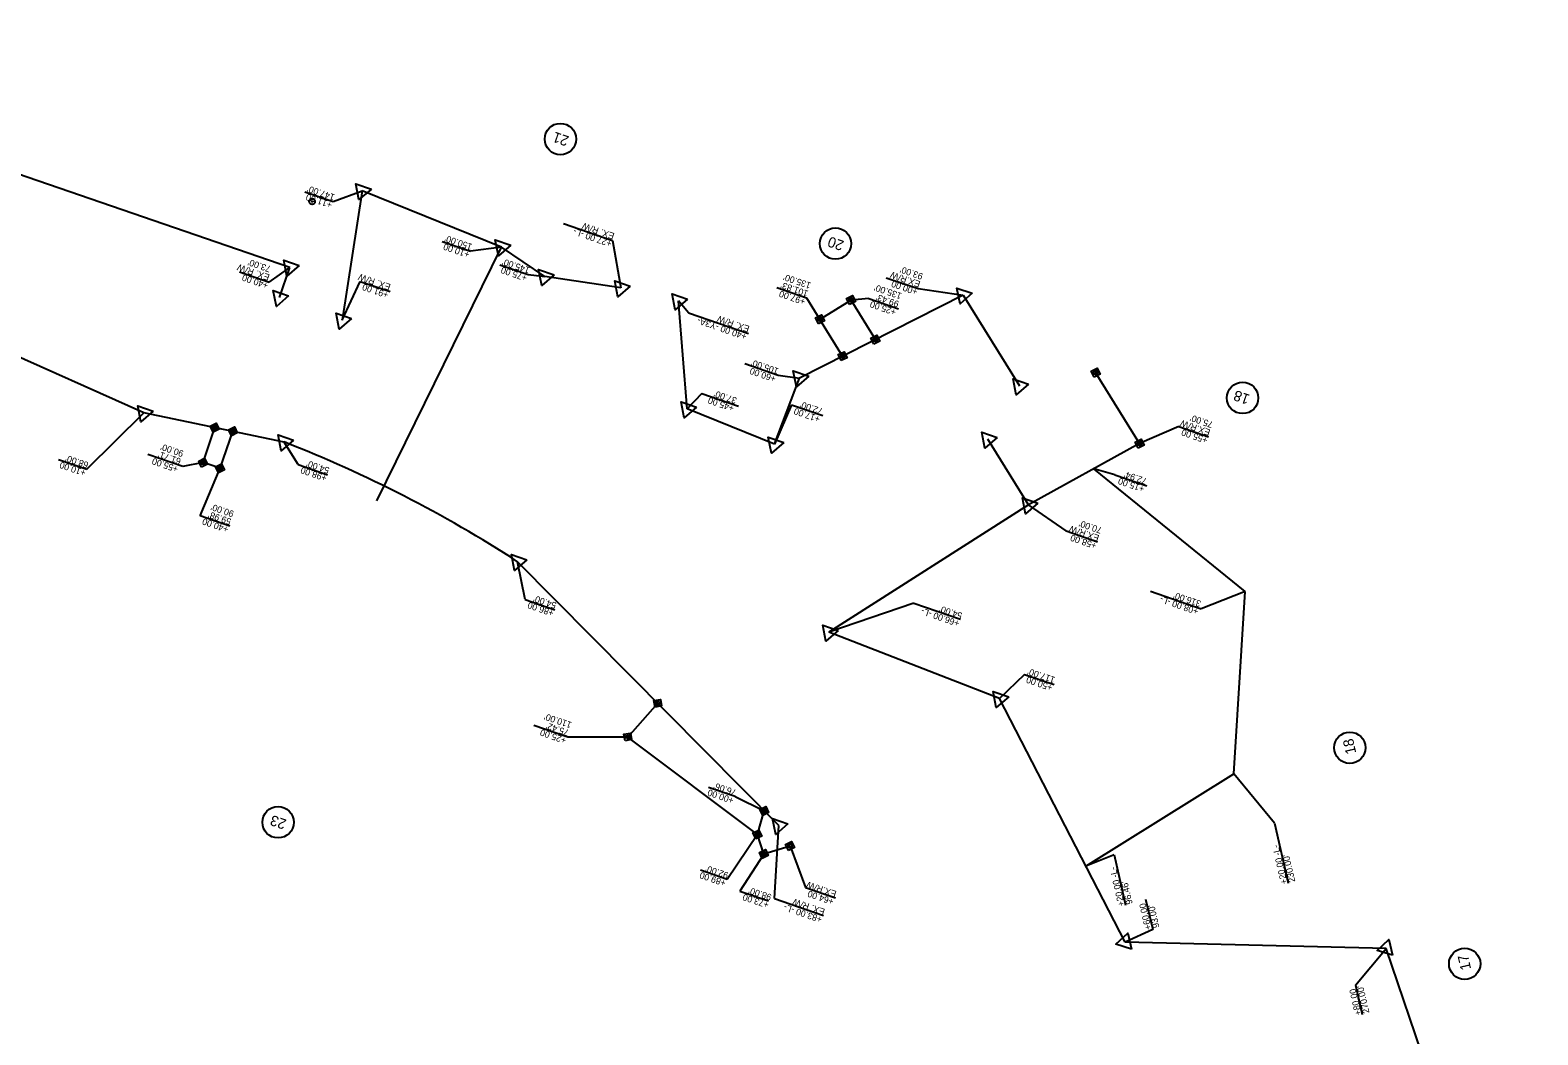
# Model space of a CAD drawing. Extents: x 474184 to 481900, y 489262 to 505659.
# Drawn here: x 480329 to 481484, y 492769 to 493539 of the extents above; entities that cross this region are included whole.
import ezdxf

# ---------------------------------------------------------------- set-up
doc = ezdxf.new("R2010")
doc.units = 0
for name, color, linetype in [('Default', 7, 'Continuous'), ('Prop Drainage Structure Drop Inlet Grate 2 Wide Slots and Sag Grates 840 22 CELL', 7, 'Continuous'), ('Prop Drainage Structure Outlet Berm Ditch 850 10 Label', 7, 'Continuous'), ('Prop Drainage Structure Pipe CSP 15in', 7, 'Continuous'), ('Prop Drainage Structure Pipe RCP 18in Class IV', 7, 'Continuous'), ('Prop Drainage Structure Pipe RCP 18in Class IV Label', 7, 'Continuous'), ('Prop Drainage Structure Pipe Side Drain 15in Label', 7, 'Continuous'), ('Prop Drainage Structure Pipe Stub Out CELL', 7, 'Continuous'), ('Prop Drainage Structure Plot Symbol 50 Scale', 7, 'Continuous'), ('Prop Earthen Structure Base Ditch Lateral Detail Label', 7, 'Continuous'), ('Prop Earthen Structure False Sump CELL', 7, 'Continuous'), ('Prop Earthen Structure False Sump Label', 7, 'Continuous'), ('Sheet Plot Border Outside CELL', 7, 'Continuous')]:
    doc.layers.add(name, color=color, linetype=linetype)

msp = doc.modelspace()

# ---------------------------------------------------------------- linework, layer by layer
at = {"layer": 'Default'}
for radius in [2.18, 0.24]:
    msp.add_circle((480544.7, 493407.3), radius, dxfattribs=at)
at = {"layer": 'Prop Drainage Structure Drop Inlet Grate 2 Wide Slots and Sag Grates 840 22 CELL'}
for p, q in [((480957.5, 493331.9), (480933.7, 493317.1)), ((480976.2, 493301.6), (480957.5, 493331.9)), ((480951.1, 493288.9), (480933.7, 493317.1)), ((481178.6, 493221.9), (481144.9, 493276.3)), ((481178.6, 493221.9), (481093.5, 493175)), ((480786.5, 492997.2), (480809.4, 493023.1)), ((480885.8, 492922.5), (480786.5, 492997.2))]:
    msp.add_line(p, q, dxfattribs=at)
at = {"layer": 'Prop Drainage Structure Outlet Berm Ditch 850 10 Label'}
for p, q in [((480461.2, 493207.4), (480470.1, 493234.2)), ((480474.2, 493203), (480484, 493231.3)), ((480474.2, 493203), (480461.2, 493207.4)), ((480885.8, 492922.5), (480891, 492940.7)), ((480890.7, 492907.6), (480885.8, 492922.5)), ((480910.8, 492913.7), (480890.7, 492907.6))]:
    msp.add_line(p, q, dxfattribs=at)
at = {"layer": 'Prop Drainage Structure Pipe CSP 15in'}
for p, q in [((480734.9, 493455.2), (480734.9, 493455.2)), ((480945.6, 493375.1), (480945.6, 493375.1)), ((481257.5, 493256.9), (481257.5, 493256.9)), ((481339.6, 492989), (481339.6, 492989)), ((480518.6, 492931.9), (480518.6, 492931.9)), ((481427.6, 492823.5), (481427.6, 492823.5))]:
    msp.add_line(p, q, dxfattribs=at)
for centre in [(480734.9, 493455.2), (480945.6, 493375.1), (481257.5, 493256.9), (481339.6, 492989), (480518.6, 492931.9), (481427.6, 492823.5)]:
    msp.add_circle(centre, 12, dxfattribs=at)
at = {"layer": 'Prop Drainage Structure Pipe RCP 18in Class IV'}
for p, q in [((480583, 493415.6), (480583, 493415.6)), ((480689.8, 493372.5), (480689.8, 493372.5)), ((480527.7, 493356.9), (480527.7, 493356.9)), ((480723, 493349.9), (480723, 493349.9)), ((480519.6, 493333.8), (480519.6, 493333.8)), ((480781.2, 493341.2), (480781.2, 493341.2)), ((480825.3, 493331.2), (480825.3, 493331.2)), ((480957.5, 493331.9), (480957.5, 493331.9)), ((481043.3, 493335.7), (481043.3, 493335.7)), ((480567.8, 493316.4), (480567.8, 493316.4)), ((480933.7, 493317.1), (480933.7, 493317.1)), ((480976.2, 493301.6), (480976.2, 493301.6)), ((480951.1, 493288.9), (480951.1, 493288.9)), ((480918, 493272.1), (480918, 493272.1)), ((481144.9, 493276.3), (481144.9, 493276.3)), ((481086.5, 493266.1), (481086.5, 493266.1)), ((480415.9, 493245.5), (480415.9, 493245.5)), ((480832.1, 493248.5), (480832.1, 493248.5)), ((480470.1, 493234.2), (480470.1, 493234.2)), ((480484, 493231.3), (480484, 493231.3)), ((480523.4, 493223.1), (480523.4, 493223.1)), ((480898.9, 493221.4), (480898.9, 493221.4)), ((481062.4, 493225.3), (481062.4, 493225.3)), ((481178.6, 493221.9), (481178.6, 493221.9)), ((480461.2, 493207.4), (480461.2, 493207.4)), ((480474.2, 493203), (480474.2, 493203)), ((481093.5, 493175), (481093.5, 493175)), ((480702.1, 493131.5), (480702.1, 493131.5)), ((480940.5, 493077.5), (480940.5, 493077.5)), ((480809.4, 493023.1), (480809.4, 493023.1)), ((481071.2, 493026.6), (481071.2, 493026.6)), ((480786.5, 492997.2), (480786.5, 492997.2)), ((480891, 492940.7), (480891, 492940.7)), ((480902.2, 492929.4), (480902.2, 492929.4)), ((480885.8, 492922.5), (480885.8, 492922.5)), ((480890.7, 492907.6), (480890.7, 492907.6)), ((480910.8, 492913.7), (480910.8, 492913.7)), ((481167.4, 492840.1), (481167.4, 492840.1)), ((481367.5, 492835.2), (481367.5, 492835.2))]:
    msp.add_line(p, q, dxfattribs=at)
for points in [[(480590.1, 493416.9), (480580.6, 493408.8), (480578.2, 493421)], [(480696.9, 493373.9), (480687.4, 493365.7), (480685, 493378)], [(480534.7, 493358.3), (480525.3, 493350.1), (480522.9, 493362.4)], [(480730.1, 493351.3), (480720.6, 493343.1), (480718.2, 493355.3)], [(480788.3, 493342.5), (480778.9, 493334.4), (480776.5, 493346.6)], [(480526.7, 493335.1), (480517.3, 493327), (480514.9, 493339.2)], [(480832.3, 493332.6), (480822.9, 493324.4), (480820.5, 493336.6)], [(481050.4, 493337.1), (481041, 493328.9), (481038.6, 493341.1)], [(480574.9, 493317.8), (480565.5, 493309.6), (480563.1, 493321.9)], [(480925.1, 493273.5), (480915.7, 493265.3), (480913.3, 493277.6)], [(481093.6, 493267.5), (481084.1, 493259.3), (481081.7, 493271.5)], [(480423, 493246.8), (480413.6, 493238.7), (480411.2, 493250.9)], [(480839.2, 493249.9), (480829.8, 493241.7), (480827.4, 493253.9)], [(480530.5, 493224.5), (480521, 493216.3), (480518.6, 493228.6)], [(480906, 493222.8), (480896.5, 493214.6), (480894.1, 493226.8)], [(481069.5, 493226.6), (481060, 493218.5), (481057.6, 493230.7)], [(481100.6, 493176.4), (481091.2, 493168.2), (481088.8, 493180.5)], [(480709.2, 493132.8), (480699.8, 493124.7), (480697.4, 493136.9)], [(480947.6, 493078.8), (480938.2, 493070.6), (480935.8, 493082.9)], [(481078.3, 493028), (481068.8, 493019.8), (481066.5, 493032.1)], [(480909.2, 492930.8), (480899.8, 492922.6), (480897.4, 492934.9)], [(481172.3, 492834.8), (481160.4, 492838.5), (481169.5, 492847)], [(481372.4, 492830), (481360.5, 492833.6), (481369.6, 492842.1)]]:
    msp.add_lwpolyline(points, close=True, dxfattribs=at)
at = {"layer": 'Prop Drainage Structure Pipe RCP 18in Class IV Label'}
for points in [[(480956.3, 493328.5), (480954.1, 493333), (480958.6, 493335.3), (480960.9, 493330.7)], [(480956.9, 493330.2), (480955.8, 493332.5), (480958, 493333.6), (480959.2, 493331.3)], [(480932.5, 493313.7), (480930.3, 493318.3), (480934.8, 493320.5), (480937.1, 493315.9)], [(480933.1, 493315.4), (480932, 493317.7), (480934.2, 493318.8), (480935.4, 493316.5)], [(480975, 493298.2), (480972.8, 493302.8), (480977.4, 493305), (480979.6, 493300.5)], [(480975.6, 493299.9), (480974.5, 493302.2), (480976.8, 493303.3), (480977.9, 493301)], [(480950, 493285.5), (480947.7, 493290.1), (480952.3, 493292.3), (480954.5, 493287.7)], [(480950.6, 493287.2), (480949.4, 493289.5), (480951.7, 493290.6), (480952.8, 493288.3)], [(481143.7, 493272.9), (481141.5, 493277.4), (481146.1, 493279.7), (481148.3, 493275.1)], [(481144.3, 493274.6), (481143.2, 493276.9), (481145.5, 493278), (481146.6, 493275.7)], [(480468.9, 493230.8), (480466.7, 493235.4), (480471.3, 493237.6), (480473.5, 493233)], [(480469.5, 493232.5), (480468.4, 493234.8), (480470.7, 493235.9), (480471.8, 493233.6)], [(480482.9, 493227.9), (480480.6, 493232.5), (480485.2, 493234.7), (480487.4, 493230.2)], [(480483.4, 493229.6), (480482.3, 493231.9), (480484.6, 493233), (480485.7, 493230.7)], [(481177.4, 493218.5), (481175.2, 493223.1), (481179.8, 493225.3), (481182, 493220.7)], [(481178, 493220.2), (481176.9, 493222.5), (481179.2, 493223.6), (481180.3, 493221.3)], [(480460, 493204), (480457.8, 493208.5), (480462.3, 493210.8), (480464.6, 493206.2)], [(480460.6, 493205.7), (480459.5, 493208), (480461.8, 493209.1), (480462.9, 493206.8)], [(480473, 493199.6), (480470.8, 493204.1), (480475.3, 493206.4), (480477.6, 493201.8)], [(480473.6, 493201.3), (480472.5, 493203.5), (480474.8, 493204.7), (480475.9, 493202.4)], [(480807.4, 493020.1), (480806.5, 493025.1), (480811.5, 493026), (480812.4, 493021)], [(480808.4, 493021.6), (480807.9, 493024.1), (480810.4, 493024.6), (480810.9, 493022.1)], [(480784.4, 492994.3), (480783.5, 492999.3), (480788.5, 493000.2), (480789.4, 492995.2)], [(480785.4, 492995.7), (480785, 492998.2), (480787.5, 492998.7), (480787.9, 492996.2)], [(480889.9, 492937.2), (480887.6, 492941.8), (480892.2, 492944.1), (480894.4, 492939.5)], [(480890.4, 492939), (480889.3, 492941.2), (480891.6, 492942.4), (480892.7, 492940.1)], [(480884.6, 492919.1), (480882.4, 492923.7), (480886.9, 492925.9), (480889.2, 492921.3)], [(480885.2, 492920.8), (480884.1, 492923.1), (480886.3, 492924.2), (480887.5, 492921.9)], [(480909.7, 492910.3), (480907.4, 492914.8), (480912, 492917.1), (480914.2, 492912.5)], [(480910.2, 492912), (480909.1, 492914.2), (480911.4, 492915.4), (480912.5, 492913.1)], [(480889.5, 492904.2), (480887.3, 492908.7), (480891.9, 492911), (480894.1, 492906.4)], [(480890.1, 492905.9), (480889, 492908.1), (480891.3, 492909.3), (480892.4, 492907)]]:
    msp.add_lwpolyline(points, close=True, dxfattribs=at)
at = {"layer": 'Prop Drainage Structure Pipe Side Drain 15in Label'}
for p, q in [((480527.7, 493356.9), (479998.1, 493538.6)), ((480689.8, 493372.5), (480583, 493415.6)), ((480723, 493349.9), (480689.8, 493372.5)), ((480519.6, 493333.8), (480527.7, 493356.9)), ((480781.2, 493341.2), (480723, 493349.9)), ((480832.1, 493248.5), (480825.3, 493331.2)), ((481043.3, 493335.7), (480918, 493272.1)), ((481043.3, 493335.7), (481086.5, 493266.1)), ((480415.9, 493245.5), (480241.2, 493323.4)), ((480898.9, 493221.4), (480918, 493272.1)), ((480523.4, 493223.1), (480415.9, 493245.5)), ((480898.9, 493221.4), (480832.1, 493248.5)), ((481093.5, 493175), (481062.4, 493225.3)), ((481093.5, 493175), (480940.5, 493077.5)), ((480902.2, 492929.4), (480702.1, 493131.5)), ((481071.2, 493026.6), (480940.5, 493077.5)), ((481167.4, 492840.1), (481071.2, 493026.6)), ((481367.5, 492835.2), (481167.4, 492840.1)), ((481483.7, 492492.2), (481367.5, 492835.2))]:
    msp.add_line(p, q, dxfattribs=at)
msp.add_arc((480155.9, 492286.7), 1006, 57.1152, 68.5743, dxfattribs=at)
at = {"layer": 'Prop Drainage Structure Pipe Stub Out CELL'}
for p, q in [((481259.4, 493108.7), (481143.5, 493202.6)), ((481250.7, 492968.9), (481259.4, 493108.7)), ((481137.4, 492898.2), (481250.7, 492968.9))]:
    msp.add_line(p, q, dxfattribs=at)
at = {"layer": 'Prop Drainage Structure Plot Symbol 50 Scale'}
for p, q in [((480539.1, 493414.7), (480560.7, 493407.3)), ((480583, 493415.6), (480567.8, 493316.4)), ((480737.3, 493390.5), (480774.9, 493377.6)), ((480644.4, 493376.7), (480666, 493369.2)), ((480689.8, 493372.5), (480666, 493369.2)), ((480489, 493353.5), (480511.7, 493345.7)), ((480688.5, 493358.8), (480710.1, 493351.4)), ((480581.6, 493346.2), (480604.4, 493338.4)), ((480984.5, 493349), (481009, 493340.6)), ((480833, 493322.2), (480879.1, 493306.3)), ((480876.2, 493283.2), (480901.7, 493274.4)), ((480843.2, 493260.2), (480871.4, 493250.5)), ((480911.9, 493251.6), (480935.8, 493243.4)), ((480350.4, 493209.7), (480372, 493202.3)), ((480533.9, 493205.9), (480556.6, 493198)), ((481122.3, 493155), (481146.4, 493146.7)), ((480707.8, 493102.5), (480730.5, 493094.7)), ((481005.7, 493099.7), (481041.5, 493087.4)), ((481090.4, 493045.2), (481113.2, 493037.3)), ((480898.9, 492873.4), (480902.2, 492929.4)), ((480898.9, 492873.4), (480936.5, 492860.4)), ((481183.2, 492873.1), (481188.6, 492849.7)), ((481344, 492807.1), (481349.1, 492784.8))]:
    msp.add_line(p, q, dxfattribs=at)
for points in [[(480560.7, 493407.3), (480583, 493415.6)], [(480774.9, 493377.6), (480781.2, 493341.2)], [(480511.7, 493345.7), (480527.7, 493356.9)], [(480567.8, 493316.4), (480581.6, 493346.2)], [(480710.1, 493351.4), (480723, 493349.9)], [(480833, 493322.2), (480825.3, 493331.2)], [(481009, 493340.6), (481043.3, 493335.7)], [(480901.7, 493274.4), (480918, 493272.1)], [(480843.2, 493260.2), (480832.1, 493248.5)], [(480911.9, 493251.6), (480898.9, 493221.4)], [(480372, 493202.3), (480415.9, 493245.5)], [(480533.9, 493205.9), (480523.4, 493223.1)], [(481122.3, 493155), (481093.5, 493175)], [(480707.8, 493102.5), (480702.1, 493131.5)], [(481005.7, 493099.7), (480940.5, 493077.5)], [(481090.4, 493045.2), (481071.2, 493026.6)], [(481188.6, 492849.7), (481167.4, 492840.1)], [(481344, 492807.1), (481367.5, 492835.2)]]:
    msp.add_lwpolyline(points, dxfattribs=at)
at = {"layer": 'Prop Earthen Structure Base Ditch Lateral Detail Label'}
for p, q in [((480445.7, 493204.3), (480418.8, 493213.5)), ((480461.2, 493207.4), (480445.7, 493204.3)), ((480459, 493166.5), (480474.2, 493203)), ((480481.7, 493158.7), (480459, 493166.5)), ((480868.8, 492951.6), (480848.4, 492958.6)), ((480868.8, 492951.6), (480891, 492940.7)), ((480885.8, 492922.5), (480862.7, 492888.2)), ((480890.7, 492907.6), (480872.3, 492879.2)), ((480910.8, 492913.7), (480922.6, 492881.9)), ((480862.7, 492888.2), (480842.3, 492895.2)), ((480922.6, 492881.9), (480945.5, 492874.1)), ((480872.3, 492879.2), (480894.3, 492871.7))]:
    msp.add_line(p, q, dxfattribs=at)
at = {"layer": 'Prop Earthen Structure False Sump CELL'}
for p, q in [((480900.6, 493341.4), (480923.3, 493333.5)), ((480971.1, 493333), (480993.8, 493325.1)), ((481208.7, 493235), (481231.4, 493227.1)), ((480740.6, 492997), (480714.5, 493006)), ((480786.5, 492997.2), (480740.6, 492997))]:
    msp.add_line(p, q, dxfattribs=at)
for points in [[(480923.3, 493333.5), (480933.7, 493317.1)], [(480971.1, 493333), (480957.5, 493331.9)], [(481208.7, 493235), (481178.6, 493221.9)]]:
    msp.add_lwpolyline(points, dxfattribs=at)
at = {"layer": 'Prop Earthen Structure False Sump Label'}
for p, q in [((481159.7, 493198), (481184.2, 493189.5)), ((481187, 493108.8), (481225.7, 493095.5)), ((481281.8, 492931.2), (481292.4, 492885.3)), ((481159, 492906.9), (481167.9, 492868.3))]:
    msp.add_line(p, q, dxfattribs=at)
for points in [[(481159.7, 493198), (481143.5, 493202.6)], [(481259.4, 493108.7), (481225.7, 493095.5)], [(481281.8, 492931.2), (481250.7, 492968.9)], [(481159, 492906.9), (481137.4, 492898.2)]]:
    msp.add_lwpolyline(points, dxfattribs=at)
at = {"layer": 'Sheet Plot Border Outside CELL'}
msp.add_line((480594.2, 493178.2), (480689.8, 493372.5), dxfattribs=at)

# ---------------------------------------------------------------- texts
at = {"layer": 'Prop Drainage Structure Pipe CSP 15in'}
for s, rotation, p in [('21', 160.9892, (480742, 493457)), ('20', 160.9892, (480952.7, 493376.9)), ('18', 160.9892, (481263.6, 493259.1)), ('18', 102.9811, (481344.6, 492985)), ('23', 160.9892, (480525.6, 492933.7)), ('17', 102.9811, (481432.6, 492819.6))]:
    msp.add_text(s, height=8, rotation=rotation, dxfattribs=at).set_placement(p)
at = {"layer": 'Prop Drainage Structure Plot Symbol 50 Scale'}
for s, rotation, p in [('+11.00', 160.9982, (480560.5, 493406.7)), ("147.00'", 160.9982, (480562.5, 493412.6)), ('EX. R/W', 160.9982, (480776.7, 493382.9)), ("150.00'", 160.9982, (480667.8, 493374.6)), ('+27.00 -L-', 160.9982, (480774.7, 493377)), ('+10.00', 160.9982, (480665.8, 493368.7)), ('EX. R/W', 160.9982, (480512.6, 493351.3)), ("73.00'", 160.9982, (480513.5, 493357.6)), ('+75.00', 160.9982, (480709.9, 493350.8)), ("145.00'", 160.9982, (480711.9, 493356.7)), ('EX.R/W', 160.9892, (481011.1, 493346.1)), ("93.00'", 160.9892, (481013.1, 493352)), ('+40.00', 160.9982, (480511.6, 493345)), ('EX. R/W', 160.9982, (480605.3, 493343.9)), ('+91.00', 160.9982, (480603.7, 493337.8)), ('+00.00', 160.9892, (481009, 493340.2)), ('EX. R/W', 160.9892, (480880.2, 493311.8)), ('+40.00 -Y3A- ', 160.9892, (480878.1, 493305.9)), ("105.00'", 160.9892, (480902.5, 493279.4)), ('+60.00 ', 160.9892, (480900.5, 493273.5)), ("37.00'", 160.9892, (480870.5, 493256.9)), ('+45.00 ', 160.9892, (480868.5, 493251)), ('+17.00 ', 160.9892, (480934.3, 493242.7)), ("72.00'", 160.9892, (480936.4, 493248.6)), ('+10.00', 160.9892, (480371.8, 493201.5)), ("68.00'", 160.9892, (480373.8, 493207.5)), ('+98.00', 160.9982, (480556.4, 493197.5)), ("54.00'", 160.9982, (480558.4, 493203.4)), ('EX.R/W', 160.9892, (481148.1, 493151.6)), ("70.00'", 160.9892, (481150.2, 493157.5)), ('+58.00', 160.9892, (481146.1, 493145.7)), ('+86.00', 160.9982, (480730.3, 493094.1)), ("54.00'", 160.9982, (480732.3, 493100)), ('+66.00 -L-', 160.9892, (481041.1, 493086.2)), ("54.00'", 160.9892, (481043.2, 493092.1)), ('+50.00', 160.9892, (481112.3, 493037)), ("117.00'", 160.9892, (481114.3, 493042.9)), ('+83.00 -L-', 160.9892, (480935.9, 492859.4)), ('EX. R/W', 160.9892, (480938, 492865.3)), ('+60.00', 102.9811, (481187.7, 492850.2)), ("93.00'", 102.9811, (481193.8, 492851.6)), ('+80.00', 102.9811, (481348.6, 492784.7)), ("270.00'", 102.9811, (481354.7, 492786.1))]:
    msp.add_text(s, height=5, rotation=rotation, dxfattribs=at).set_placement(p)
at = {"layer": 'Prop Earthen Structure Base Ditch Lateral Detail Label'}
for s, rotation, p in [("61.71'", 160.9892, (480444.7, 493210.3)), ("90.00'", 160.9892, (480446.7, 493216.2)), ('+55.00', 160.9892, (480442.6, 493204.4)), ("59.98'", 160.9892, (480483.2, 493164.2)), ("90.00' ", 160.9892, (480485.2, 493170.1)), ('+40.00', 160.9892, (480481.1, 493158.2)), ("76.06'", 160.9892, (480870.2, 492956.6)), ('+00.00', 160.9892, (480868.2, 492950.6)), ('+89.00', 160.9892, (480862.1, 492887.3)), ("92.00'", 160.9892, (480864.1, 492893.2)), ("98.00'", 161.2815, (480897.1, 492876.5)), ('EX.R/W', 160.9892, (480946.8, 492879)), ('+64.00', 160.9892, (480944.8, 492873.1)), ('+73.00', 161.2815, (480895.1, 492870.6))]:
    msp.add_text(s, height=5, rotation=rotation, dxfattribs=at).set_placement(p)
at = {"layer": 'Prop Earthen Structure False Sump CELL'}
for s, rotation, p in [("101.83'", 160.9892, (480925.2, 493338.8)), ("135.00'", 160.9892, (480927.3, 493345)), ("135.00'", 160.9892, (480996.8, 493337)), ('+97.00', 160.9892, (480923, 493332.6)), ('+25.00', 160.9892, (480992.6, 493324.6)), ("99.43'", 160.9892, (480994.7, 493330.8)), ('EX.R/W', 160.9892, (481233.2, 493232.5)), ("75.00'", 160.9892, (481235.3, 493238.4)), ('+55.00', 160.9892, (481231.2, 493226.5)), ("110.00'", 160.9857, (480744, 493008.4)), ("75.42'", 160.9857, (480741.9, 493002.5)), ('+25.00', 160.9857, (480739.9, 492996.6))]:
    msp.add_text(s, height=5, rotation=rotation, dxfattribs=at).set_placement(p)
at = {"layer": 'Prop Earthen Structure False Sump Label'}
for s, rotation, p in [('+15.00', 160.9892, (481182.7, 493189.2)), ("72.94'", 160.9892, (481184.7, 493195.1)), ('+08.00 -L-', 161.0874, (481224.1, 493095.4)), ("316.00'", 161.0874, (481226.1, 493101.3)), ('+20.00 -L-', 102.9811, (481291.8, 492885.1)), ("230.00'", 102.9811, (481297.9, 492886.5)), ('+20.00 -L-', 102.9811, (481167.2, 492868.2)), ("96.46'", 102.9811, (481173.3, 492869.6))]:
    msp.add_text(s, height=5, rotation=rotation, dxfattribs=at).set_placement(p)

doc.saveas('drawing.dxf')
